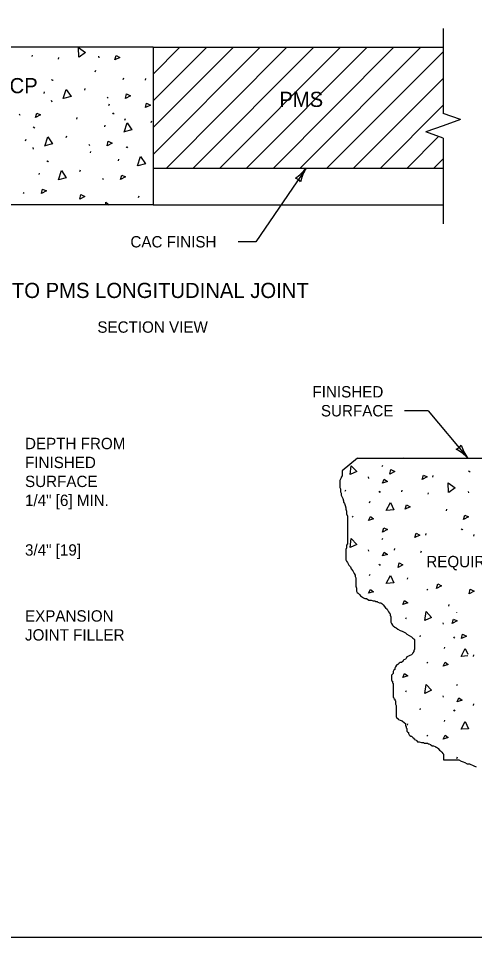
# Model space of a CAD drawing. Extents: x 49979.1 to 50021, y 49966.7 to 50011.4.
# Drawn here: x 50009.012 to 50011.424, y 49987.799 to 49992.652 of the extents above; entities that cross this region are included whole.
import ezdxf

# ---------------------------------------------------------------- set-up
doc = ezdxf.new("R2010")
doc.units = 0
for name, color, linetype in [('Level 1', 7, 'Continuous'), ('Level 12', 7, 'Continuous'), ('Level 13', 7, 'Continuous'), ('Level 2', 7, 'Continuous'), ('Level 3', 7, 'Continuous'), ('Level 6', 7, 'Continuous')]:
    doc.layers.add(name, color=color, linetype=linetype)

msp = doc.modelspace()

# ---------------------------------------------------------------- linework, layer by layer
at = {"layer": 'Level 1'}
for p, q in [((50009.7246, 49992.4991), (50008.214, 49992.4991)), ((50009.7246, 49992.4991), (50011.2574, 49992.499)), ((50009.7246, 49992.4991), (50009.7246, 49991.6675)), ((50009.7246, 49992.2157), (50010.008, 49992.4991)), ((50009.7246, 49992.3571), (50009.8666, 49992.4991)), ((50009.7246, 49991.9329), (50010.2908, 49992.499)), ((50009.7291, 49992.0788), (50010.1494, 49992.499)), ((50009.7946, 49991.8615), (50010.4322, 49992.499)), ((50009.9361, 49991.8615), (50010.5736, 49992.499)), ((50010.0775, 49991.8615), (50010.715, 49992.499)), ((50010.2189, 49991.8615), (50010.8564, 49992.499)), ((50010.3603, 49991.8615), (50010.9979, 49992.499)), ((50010.5018, 49991.8615), (50011.1393, 49992.499)), ((50010.6432, 49991.8615), (50011.2574, 49992.4757)), ((50010.7846, 49991.8615), (50011.2574, 49992.3342)), ((50010.926, 49991.8615), (50011.2574, 49992.1928)), ((50011.0674, 49991.8615), (50011.234, 49992.028)), ((50011.2089, 49991.8615), (50011.2574, 49991.91)), ((50009.7246, 49991.8615), (50011.2562, 49991.8615)), ((50009.7246, 49991.6675), (50008.214, 49991.6675)), ((50009.7246, 49991.6675), (50011.2548, 49991.6675)), ((50010.8049, 49990.3296), (50011.972, 49990.3296))]:
    msp.add_line(p, q, dxfattribs=at)
msp.add_lwpolyline([(49999.3835, 49998.9992), (50016.7501, 49998.9992), (50016.7501, 49987.7988), (49999.3835, 49987.7988)], close=True, dxfattribs=at)
for points in [[(50010.8049, 49990.3296), (50010.7234, 49990.2627), (50010.7234, 49990.2553), (50010.7234, 49990.2517), (50010.7234, 49990.2444), (50010.7234, 49990.237), (50010.7193, 49990.2297), (50010.7193, 49990.2261), (50010.7153, 49990.2187), (50010.7113, 49990.2114), (50010.7113, 49990.2077), (50010.7113, 49990.2004), (50010.7113, 49990.1967), (50010.7113, 49990.1894), (50010.7113, 49990.182), (50010.7113, 49990.1747), (50010.7153, 49990.1674), (50010.7153, 49990.1637), (50010.7153, 49990.1564), (50010.7153, 49990.1527), (50010.7193, 49990.1454), (50010.7193, 49990.1344), (50010.7234, 49990.1234), (50010.7274, 49990.1161), (50010.7314, 49990.1051), (50010.7314, 49990.0978), (50010.7355, 49990.0904), (50010.7395, 49990.0794), (50010.7435, 49990.0684), (50010.7435, 49990.0611), (50010.7475, 49990.0501), (50010.7475, 49990.0428), (50010.7475, 49990.0355), (50010.7516, 49990.0244), (50010.7516, 49990.0134), (50010.7516, 49990.0061), (50010.7516, 49989.9951), (50010.7516, 49989.9841), (50010.7516, 49989.9768), (50010.7516, 49989.9695), (50010.7516, 49989.9585), (50010.7516, 49989.9511), (50010.7516, 49989.9438), (50010.7516, 49989.9365), (50010.7516, 49989.9328), (50010.7516, 49989.9255), (50010.7516, 49989.9181), (50010.7516, 49989.9108), (50010.7516, 49989.9072), (50010.7516, 49989.8998), (50010.7516, 49989.8925), (50010.7516, 49989.8851), (50010.7516, 49989.8778), (50010.7475, 49989.8705), (50010.7475, 49989.8632), (50010.7475, 49989.8558), (50010.7435, 49989.8485), (50010.7435, 49989.8412), (50010.7435, 49989.8375), (50010.7435, 49989.8302), (50010.7435, 49989.8228), (50010.7435, 49989.8155), (50010.7435, 49989.8082), (50010.7435, 49989.8008), (50010.7435, 49989.7935), (50010.7475, 49989.7862), (50010.7516, 49989.7789), (50010.7556, 49989.7715), (50010.7596, 49989.7642), (50010.7677, 49989.7569), (50010.7717, 49989.7459), (50010.7798, 49989.7349), (50010.7838, 49989.7275), (50010.7879, 49989.7202), (50010.7919, 49989.7129), (50010.7919, 49989.7056), (50010.7959, 49989.6982), (50010.7959, 49989.6872), (50010.7959, 49989.6799), (50010.7959, 49989.6689), (50010.7959, 49989.6542), (50010.8, 49989.6432), (50010.8, 49989.6359), (50010.8, 49989.6286), (50010.804, 49989.6212), (50010.808, 49989.6176), (50010.8161, 49989.6102), (50010.8201, 49989.6029), (50010.8322, 49989.5956), (50010.8362, 49989.5919), (50010.8443, 49989.5883), (50010.8523, 49989.5883), (50010.8644, 49989.5809), (50010.8765, 49989.5809), (50010.8886, 49989.5773), (50010.8967, 49989.5773), (50010.9007, 49989.5736), (50010.9088, 49989.5736), (50010.9128, 49989.5699), (50010.9209, 49989.5663), (50010.9249, 49989.5663)], [(50010.9249, 49989.5663), (50010.9289, 49989.5663), (50010.933, 49989.5626), (50010.937, 49989.5589), (50010.941, 49989.5552), (50010.9531, 49989.5406), (50010.9612, 49989.5333), (50010.9652, 49989.5259), (50010.9692, 49989.5186), (50010.9733, 49989.5113), (50010.9773, 49989.5076), (50010.9773, 49989.5003), (50010.9813, 49989.4929), (50010.9813, 49989.4893), (50010.9813, 49989.4856), (50010.9813, 49989.4783), (50010.9813, 49989.4746), (50010.9813, 49989.471), (50010.9813, 49989.4673), (50010.9813, 49989.4636), (50010.9853, 49989.4563), (50010.9894, 49989.449), (50010.9934, 49989.4453), (50011.0015, 49989.438), (50011.0095, 49989.4343), (50011.0176, 49989.427), (50011.0297, 49989.4196), (50011.0418, 49989.416), (50011.0579, 49989.4086), (50011.066, 49989.4013), (50011.0781, 49989.394), (50011.0902, 49989.3867), (50011.0942, 49989.383), (50011.0982, 49989.3793), (50011.1023, 49989.3757), (50011.1063, 49989.372), (50011.1063, 49989.3683), (50011.1063, 49989.361), (50011.1063, 49989.3536), (50011.1063, 49989.35), (50011.1063, 49989.3463), (50011.1063, 49989.339), (50011.1063, 49989.3317), (50011.1063, 49989.3243), (50011.1063, 49989.3207), (50011.1023, 49989.3133), (50011.1023, 49989.3097), (50011.0982, 49989.3023), (50011.0942, 49989.295), (50011.0902, 49989.2913), (50011.0821, 49989.2877), (50011.074, 49989.284), (50011.066, 49989.2804), (50011.0619, 49989.273), (50011.0579, 49989.2694), (50011.0498, 49989.2657), (50011.0458, 49989.262), (50011.0458, 49989.2584), (50011.0418, 49989.2547), (50011.0378, 49989.251), (50011.0297, 49989.251), (50011.0257, 49989.2474), (50011.0216, 49989.2437), (50011.0176, 49989.24), (50011.0136, 49989.2364), (50011.0095, 49989.2364), (50011.0095, 49989.2327), (50011.0055, 49989.229), (50011.0015, 49989.2217), (50011.0015, 49989.2144), (50010.9974, 49989.2107), (50010.9934, 49989.2034), (50010.9934, 49989.1997), (50010.9934, 49989.1924), (50010.9894, 49989.1887), (50010.9853, 49989.185), (50010.9853, 49989.1777), (50010.9853, 49989.174), (50010.9853, 49989.1704), (50010.9853, 49989.1667), (50010.9853, 49989.163), (50010.9853, 49989.1594), (50010.9853, 49989.1557), (50010.9894, 49989.1521), (50010.9894, 49989.1447), (50010.9934, 49989.1411), (50010.9934, 49989.1337), (50010.9934, 49989.1264), (50010.9934, 49989.1191), (50010.9934, 49989.1117), (50010.9934, 49989.1007), (50010.9934, 49989.0934), (50010.9934, 49989.0897), (50010.9934, 49989.0824), (50010.9934, 49989.0788), (50010.9934, 49989.0714), (50010.9934, 49989.0678), (50010.9974, 49989.0641), (50010.9974, 49989.0604), (50011.0015, 49989.0568), (50011.0015, 49989.0531)], [(50011.0015, 49989.0531), (50011.0055, 49989.0494), (50011.0055, 49989.0458), (50011.0055, 49989.0384), (50011.0055, 49989.0311), (50011.0095, 49989.0238), (50011.0095, 49989.0164), (50011.0095, 49989.0055), (50011.0095, 49988.9981), (50011.0095, 49988.9871), (50011.0095, 49988.9834), (50011.0095, 49988.9761), (50011.0095, 49988.9688), (50011.0095, 49988.9651), (50011.0136, 49988.9578), (50011.0176, 49988.9578), (50011.0176, 49988.9541), (50011.0216, 49988.9505), (50011.0297, 49988.9468), (50011.0418, 49988.9431), (50011.0539, 49988.9321), (50011.0579, 49988.9285), (50011.0579, 49988.9248), (50011.0579, 49988.9211), (50011.0579, 49988.9175), (50011.0619, 49988.9138), (50011.0619, 49988.9065), (50011.066, 49988.9028), (50011.066, 49988.8955), (50011.066, 49988.8882), (50011.07, 49988.8845), (50011.074, 49988.8808), (50011.074, 49988.8772), (50011.0781, 49988.8698), (50011.0821, 49988.8662), (50011.0861, 49988.8625), (50011.0902, 49988.8625), (50011.0942, 49988.8588), (50011.0982, 49988.8551), (50011.1023, 49988.8515), (50011.1023, 49988.8478), (50011.1063, 49988.8478), (50011.1063, 49988.8441), (50011.1143, 49988.8405), (50011.1184, 49988.8368), (50011.1224, 49988.8332), (50011.1305, 49988.8332), (50011.1425, 49988.8295), (50011.1546, 49988.8295), (50011.1587, 49988.8258), (50011.1627, 49988.8258), (50011.1667, 49988.8258), (50011.1708, 49988.8258), (50011.1748, 49988.8258), (50011.1788, 49988.8222), (50011.1829, 49988.8222), (50011.1909, 49988.8185), (50011.199, 49988.8112), (50011.207, 49988.8112), (50011.2151, 49988.8075), (50011.2191, 49988.8038), (50011.2231, 49988.8038), (50011.2272, 49988.8002), (50011.2312, 49988.7965), (50011.2393, 49988.7892), (50011.2433, 49988.7855), (50011.2474, 49988.7818), (50011.2514, 49988.7782), (50011.2554, 49988.7709), (50011.2594, 49988.7672), (50011.2594, 49988.7599), (50011.2594, 49988.7562), (50011.2594, 49988.7489), (50011.2594, 49988.7452), (50011.2594, 49988.7415), (50011.2594, 49988.7379), (50011.2675, 49988.7379), (50011.2715, 49988.7379), (50011.2796, 49988.7379), (50011.2917, 49988.7379), (50011.2997, 49988.7379), (50011.3118, 49988.7379), (50011.3159, 49988.7379), (50011.3239, 49988.7379), (50011.328, 49988.7379), (50011.332, 49988.7379), (50011.336, 49988.7379), (50011.3401, 49988.7379), (50011.3521, 49988.7305), (50011.3642, 49988.7269), (50011.3723, 49988.7232), (50011.3844, 49988.7159), (50011.3965, 49988.7159), (50011.4046, 49988.7122), (50011.4126, 49988.7085), (50011.4207, 49988.7049), (50011.4328, 49988.7012)]]:
    msp.add_lwpolyline(points, dxfattribs=at)
at = {"layer": 'Level 12'}
msp.add_line((50011.0686, 49988.9207), (50011.0719, 49988.9282), dxfattribs=at)
msp.add_lwpolyline([(50011.0441, 49990.3277), (50011.0449, 49990.3296)], dxfattribs=at)
at = {"layer": 'Level 13'}
for p, q in [((50009.085, 49992.4495), (50009.0871, 49992.458)), ((50009.2242, 49992.4371), (50009.2264, 49992.4456)), ((50009.436, 49992.4518), (50009.4383, 49992.4441)), ((50009.4191, 49992.3697), (50009.4212, 49992.3782)), ((50009.1882, 49992.329), (50009.1926, 49992.3243)), ((50009.192, 49992.3276), (50009.1964, 49992.323)), ((50009.5669, 49992.3289), (50009.569, 49992.3374)), ((50009.6848, 49992.3261), (50009.6869, 49992.3346)), ((50009.148, 49992.255), (50009.1501, 49992.2635)), ((50009.3632, 49992.2722), (50009.3653, 49992.2807)), ((50009.1865, 49992.2194), (50009.1888, 49992.2117)), ((50009.4824, 49992.2356), (50009.4868, 49992.2309)), ((50009.4911, 49992.1911), (50009.4932, 49992.1996)), ((50009.0171, 49992.1479), (50009.0194, 49992.1402)), ((50009.5097, 49992.1529), (50009.5142, 49992.1482)), ((50009.5136, 49992.1515), (50009.518, 49992.1468)), ((50009.3217, 49992.1197), (50009.3238, 49992.1282)), ((50009.5759, 49992.1149), (50009.5781, 49992.1233)), ((50009.7152, 49992.1024), (50009.7173, 49992.1109)), ((50009.0908, 49992.079), (50009.0953, 49992.0744)), ((50009.0947, 49992.0776), (50009.0991, 49992.073)), ((50009.4696, 49992.0789), (50009.4717, 49992.0874)), ((50009.0507, 49992.0051), (50009.0528, 49992.0136)), ((50009.2659, 49992.0223), (50009.268, 49992.0308)), ((50009.0892, 49991.9694), (50009.0914, 49991.9617)), ((50009.385, 49991.9856), (50009.3895, 49991.9809)), ((50009.5818, 49991.9743), (50009.5862, 49991.9697)), ((50009.5856, 49991.9729), (50009.5901, 49991.9683)), ((50009.3937, 49991.9412), (50009.3959, 49991.9496)), ((50009.5416, 49991.9004), (50009.5437, 49991.9089)), ((50009.1629, 49991.9004), (50009.1673, 49991.8958)), ((50009.1667, 49991.8991), (50009.1711, 49991.8944)), ((50009.1227, 49991.8265), (50009.1248, 49991.835)), ((50009.3379, 49991.8437), (50009.34, 49991.8522)), ((50009.4571, 49991.807), (50009.4615, 49991.8024)), ((50009.0382, 49991.7332), (50009.0426, 49991.7285)), ((50009.648, 49991.7063), (50009.6501, 49991.7148)), ((50010.9351, 49990.2853), (50010.9384, 49990.2927)), ((50011.3917, 49990.2635), (50011.3961, 49990.2589)), ((50011.3956, 49990.2621), (50011.4, 49990.2575)), ((50010.8615, 49990.2308), (50010.8623, 49990.2234)), ((50011.2037, 49990.2304), (50011.2058, 49990.2389)), ((50010.7405, 49990.1559), (50010.7438, 49990.1633)), ((50011.039, 49990.1516), (50011.0411, 49990.1601)), ((50010.9178, 49990.1559), (50010.9211, 49990.1509)), ((50010.9211, 49990.154), (50010.9243, 49990.149)), ((50011.1783, 49990.1392), (50011.1804, 49990.1477)), ((50011.39, 49990.1539), (50011.3923, 49990.1462)), ((50010.8691, 49990.0948), (50010.8724, 49990.1022)), ((50011.2757, 49990.0518), (50011.2778, 49990.0603)), ((50010.7768, 49990.0231), (50010.7801, 49990.0181)), ((50011.1658, 49989.9236), (50011.1679, 49989.9321)), ((50011.3538, 49989.9568), (50011.3583, 49989.9522)), ((50011.3577, 49989.9554), (50011.3621, 49989.9508)), ((50011.42, 49989.9188), (50011.4221, 49989.9273)), ((50010.9351, 49989.9002), (50010.9384, 49989.9077)), ((50010.8615, 49989.8458), (50010.8623, 49989.8383)), ((50011.0011, 49989.8449), (50011.0032, 49989.8534)), ((50011.1404, 49989.8325), (50011.1425, 49989.841)), ((50010.9178, 49989.7708), (50010.9211, 49989.7659)), ((50010.9211, 49989.769), (50010.9243, 49989.764)), ((50010.8691, 49989.7098), (50010.8724, 49989.7172)), ((50011.0686, 49989.6908), (50011.0719, 49989.6982)), ((50011.1717, 49989.638), (50011.1749, 49989.6331)), ((50011.287, 49989.5485), (50011.2891, 49989.557)), ((50011.0604, 49989.4814), (50011.0637, 49989.4889)), ((50011.3299, 49989.5152), (50011.3309, 49989.5175)), ((50011.2563, 49989.4607), (50011.2572, 49989.4533)), ((50011.1354, 49989.3858), (50011.1387, 49989.3932)), ((50011.3126, 49989.3858), (50011.3159, 49989.3809)), ((50011.3159, 49989.384), (50011.3192, 49989.379)), ((50011.264, 49989.3247), (50011.2672, 49989.3322)), ((50011.4179, 49989.2832), (50011.42, 49989.2916)), ((50011.1717, 49989.253), (50011.1749, 49989.2481)), ((50011.0604, 49989.0964), (50011.0637, 49989.1038)), ((50011.3299, 49989.1302), (50011.3332, 49989.1376)), ((50011.2563, 49989.0757), (50011.2572, 49989.0683)), ((50011.1354, 49989.0008), (50011.1387, 49989.0082)), ((50011.3126, 49989.0008), (50011.3159, 49988.9959)), ((50011.3159, 49988.9989), (50011.3192, 49988.994)), ((50011.4179, 49989.0247), (50011.42, 49989.0332)), ((50011.264, 49988.9397), (50011.2672, 49988.9471)), ((50011.1717, 49988.868), (50011.1749, 49988.863)), ((50011.3299, 49988.7452), (50011.3332, 49988.7526))]:
    msp.add_line(p, q, dxfattribs=at)
for points in [[(50009.3322, 49992.4468), (50009.3304, 49992.498), (50009.3674, 49992.4712), (50009.333, 49992.4472)], [(50009.5219, 49992.4319), (50009.5285, 49992.4556), (50009.5483, 49992.4455), (50009.5219, 49992.4319)], [(50009.2493, 49992.2278), (50009.265, 49992.2766), (50009.2907, 49992.2387), (50009.2502, 49992.228)], [(50009.5782, 49992.229), (50009.5848, 49992.2527), (50009.6047, 49992.2427), (50009.5782, 49992.229)], [(50009.6836, 49992.1803), (50009.6902, 49992.204), (50009.71, 49992.194), (50009.6836, 49992.1803)], [(50009.1029, 49992.128), (50009.1096, 49992.1517), (50009.1294, 49992.1417), (50009.1029, 49992.128)], [(50009.5709, 49992.0517), (50009.5866, 49992.1005), (50009.6122, 49992.0626), (50009.5717, 49992.0519)], [(50009.152, 49991.9778), (50009.1677, 49992.0266), (50009.1933, 49991.9887), (50009.1528, 49991.978)], [(50009.4809, 49991.979), (50009.4875, 49992.0027), (50009.5073, 49991.9927), (50009.4809, 49991.979)], [(50009.6429, 49991.8732), (50009.6587, 49991.9219), (50009.6843, 49991.8841), (50009.6438, 49991.8733)], [(50009.224, 49991.7993), (50009.2397, 49991.8481), (50009.2654, 49991.8102), (50009.2249, 49991.7995)], [(50009.5529, 49991.8005), (50009.5595, 49991.8242), (50009.5794, 49991.8142), (50009.5529, 49991.8005)], [(50009.134, 49991.7266), (50009.1406, 49991.7503), (50009.1604, 49991.7403), (50009.134, 49991.7266)], [(50009.3367, 49991.6979), (50009.3434, 49991.7216), (50009.3632, 49991.7116), (50009.3367, 49991.6979)], [(50009.4749, 49991.6675), (50009.4744, 49991.681), (50009.4931, 49991.6675)], [(50011.05, 49990.3296), (50011.0441, 49990.3277)], [(50010.7658, 49990.243), (50010.7724, 49990.2901), (50010.8019, 49990.2596), (50010.7666, 49990.2432)], [(50010.9752, 49990.2458), (50010.9819, 49990.2695), (50011.0017, 49990.2595), (50010.9752, 49990.2458)], [(50010.9367, 49990.1987), (50010.9466, 49990.2194), (50010.9631, 49990.207), (50010.9367, 49990.1987)], [(50011.1467, 49990.2171), (50011.1533, 49990.2408), (50011.1731, 49990.2308), (50011.1467, 49990.2171)], [(50011.2862, 49990.1489), (50011.2844, 49990.2001), (50011.3214, 49990.1733), (50011.287, 49990.1494)], [(50010.9573, 49990.0536), (50010.9796, 49990.0956), (50010.9969, 49990.0569), (50010.9582, 49990.0536)], [(50011.0569, 49990.0601), (50011.0636, 49990.0838), (50011.0834, 49990.0738), (50011.0569, 49990.0601)], [(50010.8634, 49990.0016), (50010.8732, 49990.0222), (50010.8897, 49990.0099), (50010.8634, 49990.0016)], [(50011.3659, 49990.0058), (50011.3726, 49990.0295), (50011.3924, 49990.0195), (50011.3659, 49990.0058)], [(50010.9373, 49989.9391), (50010.944, 49989.9628), (50010.9638, 49989.9527), (50010.9373, 49989.9391)], [(50011.1088, 49989.9104), (50011.1154, 49989.9341), (50011.1352, 49989.924), (50011.1088, 49989.9104)], [(50010.7658, 49989.8579), (50010.7724, 49989.9051), (50010.8019, 49989.8746), (50010.7666, 49989.8582)], [(50010.9367, 49989.8137), (50010.9466, 49989.8343), (50010.9631, 49989.8219), (50010.9367, 49989.8137)], [(50011.0191, 49989.7534), (50011.0257, 49989.7771), (50011.0455, 49989.7671), (50011.0191, 49989.7534)], [(50010.9573, 49989.6685), (50010.9796, 49989.7106), (50010.9969, 49989.6718), (50010.9582, 49989.6685)], [(50010.8634, 49989.6166), (50010.8732, 49989.6372), (50010.8897, 49989.6249), (50010.8634, 49989.6166)], [(50011.2232, 49989.6427), (50011.2299, 49989.6664), (50011.2497, 49989.6564), (50011.2232, 49989.6427)], [(50011.3947, 49989.614), (50011.4013, 49989.6377), (50011.4211, 49989.6276), (50011.3947, 49989.614)], [(50011.0441, 49989.5577), (50011.0539, 49989.5783), (50011.0704, 49989.5659), (50011.0441, 49989.5577)], [(50011.1606, 49989.4729), (50011.1672, 49989.52), (50011.1967, 49989.4895), (50011.1614, 49989.4732)], [(50011.3049, 49989.457), (50011.3116, 49989.4807), (50011.3314, 49989.4707), (50011.3049, 49989.457)], [(50011.3541, 49989.3773), (50011.3608, 49989.401), (50011.3806, 49989.391), (50011.3541, 49989.3773)], [(50011.3522, 49989.2835), (50011.3744, 49989.3255), (50011.3881, 49989.2948)], [(50011.3881, 49989.2865), (50011.353, 49989.2835)], [(50011.2582, 49989.2316), (50011.2681, 49989.2522), (50011.2846, 49989.2398), (50011.2582, 49989.2316)], [(50011.0441, 49989.1727), (50011.0539, 49989.1933), (50011.0704, 49989.1809), (50011.0441, 49989.1727)], [(50011.1606, 49989.0879), (50011.1672, 49989.135), (50011.1967, 49989.1045), (50011.1614, 49989.0882)], [(50011.3316, 49989.0436), (50011.3415, 49989.0643), (50011.3579, 49989.0519), (50011.3316, 49989.0436)], [(50011.3522, 49988.8985), (50011.3744, 49988.9405), (50011.3917, 49988.9018), (50011.353, 49988.8985)], [(50011.2582, 49988.8466), (50011.2681, 49988.8672), (50011.2846, 49988.8548), (50011.2582, 49988.8466)]]:
    msp.add_lwpolyline(points, dxfattribs=at)
at = {"layer": 'Level 3'}
for p, q in [((50010.5329, 49991.8605), (50010.2671, 49991.4723)), ((50010.2671, 49991.4723), (50010.1735, 49991.4723)), ((50011.1794, 49990.5802), (50011.0534, 49990.5802)), ((50011.1794, 49990.5802), (50011.3885, 49990.3296))]:
    msp.add_line(p, q, dxfattribs=at)
for centre, radius, start, end in [((50010.3554, 49991.9945), 0.2223, 303.0582, 323.2417), ((50010.7321, 49991.7395), 0.233, 148.4295, 167.6794), ((50010.4611, 49991.7557), 0.0548, 37.741, 73.4634), ((50011.3063, 49990.428), 0.0548, 291.9765, 327.6989), ((50011.2238, 49990.1803), 0.2223, 42.1982, 62.3817), ((50011.5745, 49990.4698), 0.233, 197.7605, 217.0104)]:
    msp.add_arc(centre, radius, start, end, dxfattribs=at)
at = {"layer": 'Level 6'}
for p, q in [((50011.2574, 49992.599), (50011.2574, 49992.1494)), ((50011.3488, 49992.117), (50011.2574, 49992.1494)), ((50011.3488, 49992.117), (50011.2574, 49992.0846)), ((50011.2574, 49992.0846), (50011.166, 49992.0522)), ((50011.2574, 49992.0198), (50011.166, 49992.0522)), ((50011.2574, 49992.0198), (50011.2574, 49991.5675))]:
    msp.add_line(p, q, dxfattribs=at)

# ---------------------------------------------------------------- texts
at = {"layer": 'Level 2'}
for s, height, p in [('PCCP', 0.08, (50008.8173, 49992.2566)), ('PMS', 0.08, (50010.3916, 49992.1841)), ('CAC FINISH', 0.06, (50009.6046, 49991.4423)), ('PCCP TO PMS LONGITUDINAL JOINT', 0.08, (50008.6512, 49991.1754)), ('SECTION VIEW', 0.06, (50009.4299, 49990.992)), ('FINISHED ', 0.06, (50010.567, 49990.6502)), ('SURFACE', 0.06, (50010.6116, 49990.5502)), ('DEPTH FROM ', 0.06, (50009.0475, 49990.3773)), ('FINISHED', 0.06, (50009.0475, 49990.2773)), ('SURFACE ', 0.06, (50009.0475, 49990.1773)), ('1/4" [6] MIN.', 0.06, (50009.0475, 49990.0773)), ('3/4" [19] ', 0.06, (50009.0475, 49989.8153)), ('EXPANSION ', 0.06, (50009.0475, 49989.4669)), ('JOINT FILLER', 0.06, (50009.0475, 49989.3669))]:
    msp.add_text(s, height=height, dxfattribs=at).set_placement(p)
msp.add_text('REQUIRED', height=0.06, rotation=360, dxfattribs=at).set_placement((50011.1686, 49989.7539))

doc.saveas('drawing.dxf')
